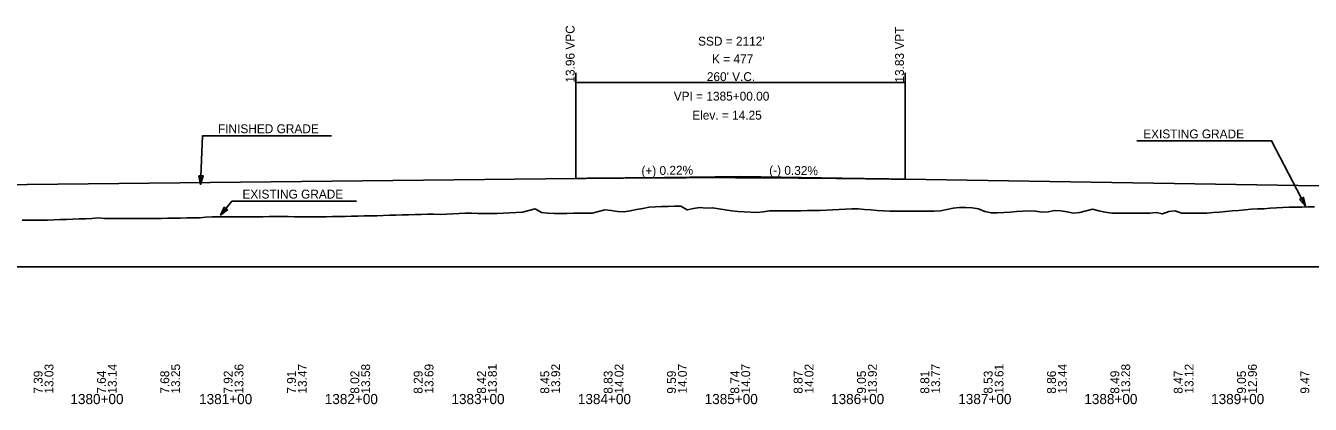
# Model space of a CAD drawing. Extents: x 2360994 to 2383826, y 330623 to 403123.
# Drawn here: x 2370361 to 2371375, y 371764 to 372063 of the extents above; entities that cross this region are included whole.
import ezdxf

# ---------------------------------------------------------------- set-up
doc = ezdxf.new("R2010")
doc.units = 0
for name, color, linetype in [('RD_DDB_GradeTX', 7, 'Continuous'), ('RD_DDB_Profile_EX', 7, 'Continuous'), ('RD_DDB_Profile_Lbl', 7, 'Continuous'), ('RD_DDB_Profile_PR', 7, 'Continuous'), ('RD_DDB_StaTX', 7, 'Continuous'), ('RD_DDB_StripGrade', 7, 'Continuous'), ('RD_DDB_VCLbl', 7, 'Continuous'), ('RD_GPK_Profile_Cell', 7, 'Continuous'), ('RD_TX_Profile', 7, 'Continuous')]:
    doc.layers.add(name, color=color, linetype=linetype)

msp = doc.modelspace()

# ---------------------------------------------------------------- linework, layer by layer
at = {"layer": 'RD_DDB_GradeTX'}
for p in [(2370845.6, 371943.2), (2371005.6, 371942.8)]:
    msp.add_line(p, (2370925.6, 371944.1), dxfattribs=at)
at = {"layer": 'RD_DDB_Profile_EX'}
for points in [[(2370373.6, 371909.8), (2370378.6, 371909.8), (2370383.6, 371910), (2370388.6, 371910.2), (2370393.6, 371910.3), (2370398.6, 371910.5), (2370403.6, 371910.7), (2370408.6, 371910.9), (2370413.6, 371911), (2370418.6, 371911.7), (2370423.6, 371911.1), (2370428.6, 371911.1), (2370433.6, 371911.1), (2370438.6, 371911.1), (2370443.6, 371911.1), (2370448.6, 371911.1), (2370453.6, 371911.1), (2370458.6, 371911.1), (2370463.6, 371911), (2370468.6, 371911), (2370473.6, 371911.2), (2370478.6, 371911.3), (2370483.6, 371911.4), (2370488.6, 371911.5), (2370493.6, 371911.5), (2370498.6, 371911.6), (2370503.6, 371912.2), (2370508.6, 371912.3), (2370513.6, 371912.4), (2370518.6, 371912.4), (2370523.6, 371912.5), (2370528.6, 371912.5), (2370533.6, 371912.5), (2370538.6, 371912.5), (2370543.6, 371912.5), (2370548.6, 371912.5), (2370553.6, 371912.6), (2370558.6, 371912.6), (2370563.6, 371912.6), (2370568.6, 371912.6), (2370573.6, 371912.5), (2370578.6, 371912.3), (2370583.6, 371912.3), (2370588.6, 371912.4), (2370593.6, 371912.5), (2370598.6, 371912.5), (2370603.6, 371912.6), (2370608.6, 371912.7), (2370613.6, 371912.7), (2370618.6, 371912.8), (2370623.6, 371912.9), (2370628.6, 371913.1), (2370633.6, 371913.2), (2370638.6, 371913.3), (2370643.6, 371913.5), (2370648.6, 371913.6), (2370653.6, 371913.7), (2370658.6, 371913.9), (2370663.6, 371914), (2370668.6, 371914.1), (2370673.6, 371914.3), (2370678.6, 371914.4), (2370683.6, 371914.4), (2370688.6, 371914.3), (2370693.6, 371914.6), (2370698.6, 371914.8), (2370703.6, 371915.1), (2370708.6, 371915.4), (2370713.6, 371915.3), (2370718.6, 371915.1), (2370723.6, 371915), (2370728.6, 371914.9), (2370733.6, 371915.1), (2370738.6, 371915.3), (2370743.6, 371915.6), (2370748.6, 371915.9), (2370753.6, 371916.1), (2370758.6, 371917.4), (2370763.6, 371918.8), (2370768.6, 371915.8), (2370773.6, 371915.2), (2370778.6, 371915), (2370783.6, 371914.9), (2370788.6, 371915), (2370793.6, 371915.3), (2370798.6, 371915.4), (2370803.6, 371915.4), (2370808.6, 371915.4), (2370813.6, 371916.5), (2370818.6, 371917.8), (2370823.6, 371917.4), (2370828.6, 371916.5), (2370833.6, 371916.2), (2370838.6, 371917.2), (2370843.6, 371918.1), (2370848.6, 371919), (2370853.6, 371919.9), (2370858.6, 371920.3), (2370863.6, 371920.5), (2370868.6, 371920.6), (2370873.6, 371920.8)], [(2370873.6, 371920.8), (2370878.6, 371920.9), (2370883.6, 371917.9), (2370888.6, 371918.9), (2370893.6, 371919.7), (2370898.6, 371919.2), (2370903.6, 371919.6), (2370908.6, 371918.7), (2370913.6, 371917.9), (2370918.6, 371917), (2370923.6, 371916.7), (2370928.6, 371916.4), (2370933.6, 371916.1), (2370938.6, 371915.8), (2370943.6, 371916.4), (2370948.6, 371917), (2370953.6, 371917), (2370958.6, 371917.1), (2370963.6, 371917.1), (2370968.6, 371917.2), (2370973.6, 371917.2), (2370978.6, 371917.3), (2370983.6, 371917.4), (2370988.6, 371917.4), (2370993.6, 371917.7), (2370998.6, 371918), (2371003.6, 371918.2), (2371008.6, 371918.5), (2371013.6, 371918.8), (2371018.6, 371918.6), (2371023.6, 371918.3), (2371028.6, 371917.9), (2371033.6, 371917.5), (2371038.6, 371917.2), (2371043.6, 371916.9), (2371048.6, 371916.9), (2371053.6, 371916.9), (2371058.6, 371916.9), (2371063.6, 371916.9), (2371068.6, 371916.9), (2371073.6, 371916.9), (2371078.6, 371916.9), (2371083.6, 371917.2), (2371088.6, 371918.2), (2371093.6, 371919.1), (2371098.6, 371919.7), (2371103.6, 371919.7), (2371108.6, 371919.4), (2371113.6, 371918.8), (2371118.6, 371916.6), (2371123.6, 371915.5), (2371128.6, 371915.5), (2371133.6, 371915.8), (2371138.6, 371916.1), (2371143.6, 371916.5), (2371148.6, 371916.8), (2371153.6, 371917.1), (2371158.6, 371916.9), (2371163.6, 371916), (2371168.6, 371916.4), (2371173.6, 371917.3), (2371178.6, 371917), (2371183.6, 371916.2), (2371188.6, 371915.4), (2371193.6, 371915.8), (2371198.6, 371917.2), (2371203.6, 371918.5), (2371208.6, 371917), (2371213.6, 371916), (2371218.6, 371915.4), (2371223.6, 371915.3), (2371228.6, 371915.3), (2371233.6, 371915.3), (2371238.6, 371915.3), (2371243.6, 371915.2), (2371248.6, 371915.2), (2371253.6, 371915.7), (2371258.6, 371914.7), (2371263.6, 371916.5), (2371268.6, 371917.1), (2371273.6, 371915.2), (2371278.6, 371915.3), (2371283.6, 371915.3), (2371288.6, 371915.3), (2371293.6, 371915.3), (2371298.6, 371915.7), (2371303.6, 371916.1), (2371308.6, 371916.6), (2371313.6, 371917.1), (2371318.6, 371917.5), (2371323.6, 371918), (2371328.6, 371918.4), (2371333.6, 371918.6), (2371338.6, 371918.8), (2371343.6, 371919.1), (2371348.6, 371919.4), (2371353.6, 371919.8), (2371358.6, 371919.9), (2371363.6, 371920), (2371368.6, 371920.1), (2371373.6, 371920.2)], [(2371373.6, 371920.2), (2371378.6, 371920.3)], [(2370358.6, 371909.8), (2370363.6, 371909.8), (2370368.6, 371909.8), (2370373.6, 371909.8)]]:
    msp.add_lwpolyline(points, dxfattribs=at)
at = {"layer": 'RD_DDB_Profile_PR'}
for p, q in [((2370026, 371934.1), (2370795.6, 371942.7)), ((2371055.6, 371942), (2371434.6, 371935.9))]:
    msp.add_line(p, q, dxfattribs=at)
msp.add_spline([(2370795.6, 371942.7), (2370800.8, 371942.7), (2370806, 371942.8), (2370811.2, 371942.8), (2370816.4, 371942.9), (2370821.6, 371942.9), (2370826.8, 371943), (2370832, 371943), (2370837.2, 371943.1), (2370842.4, 371943.1), (2370847.6, 371943.1), (2370852.8, 371943.2), (2370858, 371943.2), (2370863.2, 371943.2), (2370868.4, 371943.2), (2370873.6, 371943.2), (2370878.8, 371943.2), (2370884, 371943.3), (2370889.2, 371943.3), (2370894.4, 371943.3), (2370899.6, 371943.3), (2370904.8, 371943.3), (2370910, 371943.3), (2370915.2, 371943.3), (2370920.4, 371943.3), (2370925.6, 371943.2), (2370930.8, 371943.2), (2370936, 371943.2), (2370941.2, 371943.2), (2370946.4, 371943.2), (2370951.6, 371943.1), (2370956.8, 371943.1), (2370962, 371943.1), (2370967.2, 371943.1), (2370972.4, 371943), (2370977.6, 371943), (2370982.8, 371942.9), (2370988, 371942.9), (2370993.2, 371942.8), (2370998.4, 371942.8), (2371003.6, 371942.7), (2371008.8, 371942.7), (2371014, 371942.6), (2371019.2, 371942.6), (2371024.4, 371942.5), (2371029.6, 371942.4), (2371034.8, 371942.3), (2371040, 371942.3), (2371045.2, 371942.2), (2371050.4, 371942.1), (2371055.6, 371942)], degree=3, dxfattribs=at)
at = {"layer": 'RD_DDB_VCLbl'}
for p, q in [((2370795.6, 372025.9), (2370795.6, 371942.7)), ((2371055.6, 372025.9), (2371055.6, 371942)), ((2370795.6, 372018.3), (2371055.6, 372018.3))]:
    msp.add_line(p, q, dxfattribs=at)
at = {"layer": 'RD_GPK_Profile_Cell'}
msp.add_line((2368825.6, 371872.9), (2373925.6, 371872.9), dxfattribs=at)
at = {"layer": 'RD_TX_Profile'}
for p, q in [((2370602.7, 371976.4), (2370508.1, 371976.4)), ((2371333.6, 371972.3), (2371238.5, 371972.3)), ((2370622.5, 371924.8), (2370527.4, 371924.8))]:
    msp.add_line(p, q, dxfattribs=at)
for points in [[(2370508.1, 371976.4), (2370501, 371976.4), (2370499.4, 371938)], [(2371333.6, 371972.3), (2371344.9, 371972.3), (2371371.6, 371920.9)], [(2370527.2, 371924.8), (2370524.1, 371924.8), (2370515.1, 371913.7)]]:
    msp.add_lwpolyline(points, dxfattribs=at)
for points in [[(2370497.9, 371944.8), (2370499.4, 371938), (2370501.5, 371944.7)], [(2371366.9, 371926.1), (2371371.6, 371920.9), (2371370.1, 371927.7)], [(2370517.9, 371920.1), (2370515.1, 371913.7), (2370520.7, 371917.8)]]:
    msp.add_lwpolyline(points, close=True, dxfattribs=at)

# ---------------------------------------------------------------- texts
at = {"layer": 'RD_DDB_GradeTX'}
for s, rotation, p in [('(+) 0.22%', 0.6369, (2370847.4, 371945.3)), ('(-) 0.32%', 359.077, (2370948.2, 371945.8))]:
    msp.add_text(s, height=7, rotation=rotation, dxfattribs=at).set_placement(p)
at = {"layer": 'RD_DDB_Profile_Lbl'}
for s, p in [('VPI = 1385+00.00', (2370872.9, 372004.1)), ('Elev. = 14.25', (2370887.5, 371989.1))]:
    msp.add_text(s, height=7, dxfattribs=at).set_placement(p)
at = {"layer": 'RD_DDB_StaTX'}
for s, p in [('1380+00', (2370396.6, 371764.6)), ('1381+00', (2370498.2, 371764.6)), ('1382+00', (2370597.4, 371764.6)), ('1383+00', (2370697.4, 371764.6)), ('1384+00', (2370797.2, 371764.6)), ('1385+00', (2370897.3, 371764.6)), ('1386+00', (2370997.1, 371764.6)), ('1387+00', (2371097.5, 371764.6)), ('1388+00', (2371197, 371764.6)), ('1389+00', (2371297.1, 371764.6))]:
    msp.add_text(s, height=8, dxfattribs=at).set_placement(p)
at = {"layer": 'RD_DDB_StripGrade'}
for s, p in [('13.96 VPC', (2370794.6, 372018.3)), ('13.83 VPT', (2371054.6, 372018.3)), ('13.03', (2370383.2, 371772.9)), ('13.14', (2370433.2, 371772.9)), ('13.25', (2370483.2, 371772.9)), ('13.36', (2370533.2, 371772.9)), ('13.47', (2370583.2, 371772.9)), ('13.58', (2370633.2, 371772.9)), ('13.69', (2370683.2, 371772.9)), ('13.81', (2370733.2, 371772.9)), ('13.92', (2370783.2, 371772.9)), ('14.02', (2370833.2, 371772.9)), ('14.07', (2370883.2, 371772.9)), ('14.07', (2370933.2, 371772.9)), ('14.02', (2370983.2, 371772.9)), ('13.92', (2371033.2, 371772.9)), ('13.77', (2371083.2, 371772.9)), ('13.61', (2371133.2, 371772.9)), ('13.44', (2371183.2, 371772.9)), ('13.28', (2371233.2, 371772.9)), ('13.12', (2371283.2, 371772.9)), ('12.96', (2371333.2, 371772.9)), ('7.39', (2370374.6, 371772.8)), ('7.64', (2370424.6, 371772.8)), ('7.68', (2370474.6, 371772.8)), ('7.92', (2370524.6, 371772.8)), ('7.91', (2370574.6, 371772.8)), ('8.02', (2370624.6, 371772.8)), ('8.29', (2370674.6, 371772.8)), ('8.42', (2370724.6, 371772.8)), ('8.45', (2370774.6, 371772.8)), ('8.83', (2370824.6, 371772.8)), ('9.59', (2370874.6, 371772.8)), ('8.74', (2370924.6, 371772.8)), ('8.87', (2370974.6, 371772.8)), ('9.05', (2371024.6, 371772.8)), ('8.81', (2371074.6, 371772.8)), ('8.53', (2371124.6, 371772.8)), ('8.86', (2371174.6, 371772.8)), ('8.49', (2371224.6, 371772.8)), ('8.47', (2371274.6, 371772.8)), ('9.05', (2371324.6, 371772.8)), ('9.47', (2371374.6, 371772.8))]:
    msp.add_text(s, height=7, rotation=90, dxfattribs=at).set_placement(p)
at = {"layer": 'RD_DDB_VCLbl'}
for s, p in [("SSD = 2112'", (2370892.1, 372047.5)), ('K = 477', (2370903.1, 372033.5)), ("260' V.C.", (2370899, 372019.5))]:
    msp.add_text(s, height=7, dxfattribs=at).set_placement(p)
at = {"layer": 'RD_TX_Profile'}
for s, p in [('FINISHED GRADE', (2370513.1, 371978.4)), ('EXISTING GRADE', (2371243.5, 371974.3)), ('EXISTING GRADE', (2370532.4, 371926.8))]:
    msp.add_text(s, height=7, dxfattribs=at).set_placement(p)

doc.saveas('drawing.dxf')
